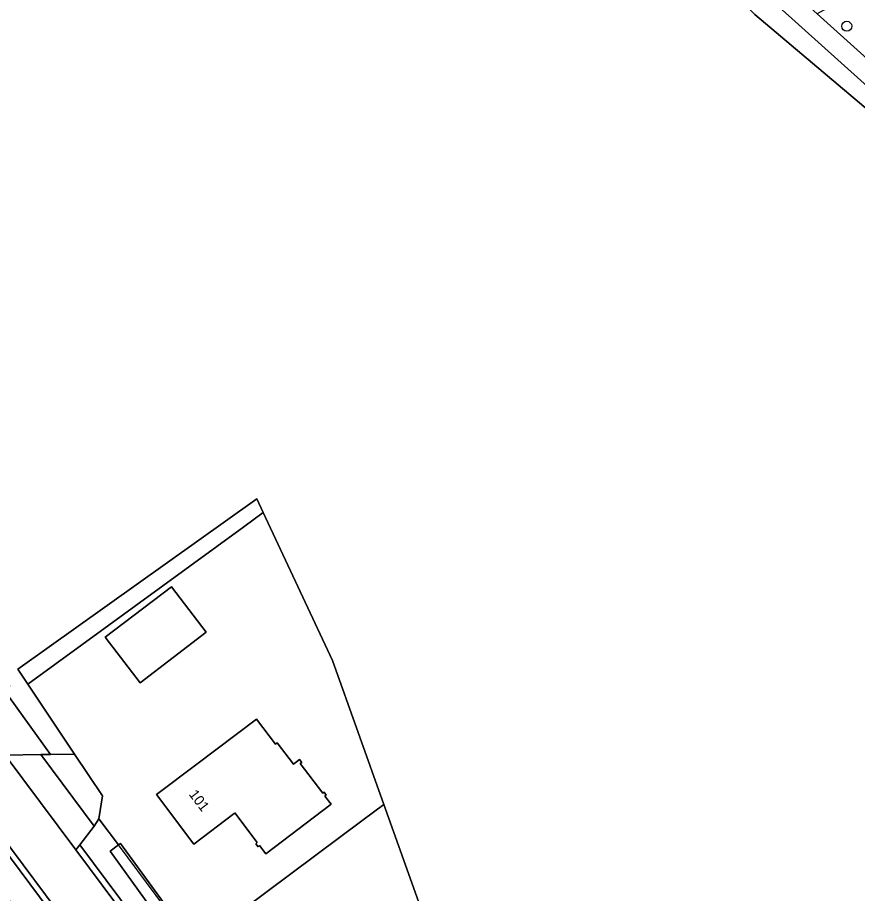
# Model space of a CAD drawing. Extents: x 164494 to 166241, y 382475 to 384495.
# Drawn here: x 164921.5 to 165004.2, y 383333.2 to 383419.5 of the extents above; entities that cross this region are included whole.
import ezdxf

# ---------------------------------------------------------------- set-up
doc = ezdxf.new("R2010")
doc.units = 0
for name, color, linetype in [('IMGEO_Berm_halfverhard', 7, 'Continuous'), ('IMGEO_Boom', 7, 'Continuous'), ('IMGEO_Bouwland', 7, 'Continuous'), ('IMGEO_Erf', 7, 'Continuous'), ('IMGEO_Grasland_overig', 7, 'Continuous'), ('IMGEO_Groenvoorziening', 7, 'Continuous'), ('IMGEO_Hek', 7, 'Continuous'), ('IMGEO_Loofbos', 7, 'Continuous'), ('IMGEO_Pand', 7, 'Continuous'), ('IMGEO_Pand_nummerreeks', 7, 'Continuous'), ('IMGEO_Parkeervlak_open', 7, 'Continuous'), ('IMGEO_Rijbaan_lokaal_gesloten', 7, 'Continuous'), ('IMGEO_Voetpad_open', 7, 'Continuous'), ('IMGEO_Waterloop', 7, 'Continuous')]:
    doc.layers.add(name, color=color, linetype=linetype)

msp = doc.modelspace()

# ---------------------------------------------------------------- linework, layer by layer
at = {"layer": 'IMGEO_Berm_halfverhard'}
msp.add_lwpolyline([(164867.512, 383408.316), (164897.147, 383368.52), (164898.891, 383366.181), (164946.531, 383302.21), (164947.016, 383302.564), (164899.311, 383366.621), (164897.533, 383369.007), (164867.994, 383408.673)], dxfattribs=at)
msp.add_lwpolyline([(164927.659, 383338.025), (164927.281, 383337.528), (164949.568, 383307.631), (164950.049, 383307.989)], close=True, dxfattribs=at)
at = {"layer": 'IMGEO_Boom'}
msp.add_circle((165003.188, 383418.608), 0.489, dxfattribs=at)
at = {"layer": 'IMGEO_Bouwland'}
for points in [[(165060.094, 383385.823), (165046.933, 383390.448), (165039.93, 383393.368), (165039.139, 383393.397), (165024.547, 383396.41), (165016.215, 383401.117), (164994.138, 383419.758), (164976.25, 383437.136), (164945.936, 383468.751), (164939.064, 383467.989)], [(164920.808, 383353.647), (164920.309, 383353.536), (164920.048, 383353.519), (164920.321, 383353.128), (164920.745, 383352.521), (164924.765, 383346.92), (164927.15, 383346.95), (164922.544, 383353.832), (164921.547, 383355.321), (164945.08, 383372.094), (164945.721, 383370.725), (164952.534, 383356.179), (164957.606, 383341.995), (164967.101, 383315.443)]]:
    msp.add_lwpolyline(points, dxfattribs=at)
at = {"layer": 'IMGEO_Erf'}
for points in [[(164952.534, 383356.179), (164945.721, 383370.725), (164943.812, 383369.334), (164922.544, 383353.832), (164927.15, 383346.95), (164929.893, 383342.853), (164929.545, 383340.596), (164931.465, 383338.015), (164931.657, 383338.164), (164938.976, 383328.124), (164955.575, 383340.483), (164957.606, 383341.995)], [(164933.586, 383353.98), (164930.165, 383358.458), (164936.684, 383363.438), (164940.105, 383358.961)], [(164945.044, 383350.408), (164946.916, 383347.935), (164947.109, 383348.081), (164948.704, 383345.973), (164949.297, 383346.422), (164949.515, 383346.135), (164949.371, 383346.027), (164951.584, 383343.103), (164951.716, 383343.202), (164951.93, 383342.919), (164951.798, 383342.82), (164952.408, 383342.014), (164945.967, 383337.14), (164945.352, 383337.954), (164945.208, 383337.845), (164944.991, 383338.132), (164945.134, 383338.241), (164942.922, 383341.164), (164942.872, 383341.126), (164938.884, 383338.108), (164935.209, 383342.965), (164939.196, 383345.983)]]:
    msp.add_lwpolyline(points, close=True, dxfattribs=at)
at = {"layer": 'IMGEO_Grasland_overig'}
for points in [[(165015.733, 383405.906), (165000.271, 383419.83), (164993.985, 383425.491), (164947.396, 383471.597), (164943.78, 383478.232), (164943.191, 383479.313), (164943.19, 383479.35), (164943.115, 383481.884), (164941.103, 383482.279), (164941.181, 383479.625), (164941.206, 383478.776), (164945.886, 383470.277), (164992.612, 383424.036), (165014.572, 383404.259)], [(165099.425, 383315.013), (165092.197, 383334.924), (165086.24, 383357.128), (165076.785, 383375.884), (165072.749, 383381.958), (165062.554, 383397.301), (165051.511, 383396.474), (165026.953, 383397.574), (165014.572, 383404.259), (164992.612, 383424.036), (164945.886, 383470.277), (164941.206, 383478.776), (164939.069, 383479.227)], [(164939.064, 383467.989), (164945.936, 383468.751), (164976.25, 383437.136), (164994.138, 383419.758), (165016.215, 383401.117), (165024.547, 383396.41), (165039.139, 383393.397), (165039.93, 383393.368), (165059.663, 383392.644), (165063.093, 383390.374), (165077.781, 383368.198), (165082.253, 383356.239), (165083.125, 383346.054), (165094.168, 383312.876)]]:
    msp.add_lwpolyline(points, dxfattribs=at)
msp.add_lwpolyline([(164922.544, 383353.832), (164943.812, 383369.334), (164945.721, 383370.725), (164945.08, 383372.094), (164921.547, 383355.321)], close=True, dxfattribs=at)
at = {"layer": 'IMGEO_Groenvoorziening'}
msp.add_lwpolyline([(165062.17, 383406.132), (165060.47, 383406.611), (165056.452, 383408.374), (165056.931, 383414.892), (165055.014, 383422.465), (165049.654, 383435.786), (165044.47, 383438.377), (165038.766, 383439.403), (165031.86, 383438.024), (165023.355, 383436.478), (165016.577, 383428.315), (165003.152, 383421.478), (165000.271, 383419.83), (165015.733, 383405.906), (165027.5, 383399.551), (165051.481, 383398.477), (165062.17, 383399.278)], close=True, dxfattribs=at)
for points in [[(164947.016, 383302.564), (164946.531, 383302.21), (164898.891, 383366.181), (164896.813, 383364.002), (164902.872, 383356.577), (164911.399, 383344.917), (164923.309, 383329.117), (164956.871, 383285.126), (164961.245, 383279.38), (164965.055, 383274.376), (164963.613, 383272.68), (164965.557, 383269.946), (164970.169, 383263.46), (164975.852, 383258.131), (164986.059, 383239.833), (164986.709, 383240.204), (164987.609, 383238.932), (164987.636, 383240.128), (164988.453, 383240.018), (165001.41, 383221.726)], [(164931.465, 383338.015), (164929.545, 383340.596), (164929.058, 383339.863), (164927.659, 383338.025), (164950.049, 383307.989), (164949.568, 383307.631), (164951.985, 383304.388), (164961.639, 383291.401), (164963.99, 383288.228), (164964.472, 383288.585), (164979.896, 383267.671), (164979.765, 383267.573), (164980.598, 383266.49)], [(164965.877, 383288.405), (164963.265, 383291.951), (164961.672, 383294.774), (164957.743, 383299.844), (164954.375, 383304.592), (164952.798, 383306.376), (164950.606, 383309.661), (164948.931, 383311.645), (164947.057, 383314.629), (164930.651, 383337.387), (164931.465, 383338.015)]]:
    msp.add_lwpolyline(points, dxfattribs=at)
at = {"layer": 'IMGEO_Hek'}
for points in [[(164943.812, 383369.334), (164945.721, 383370.725)], [(164922.544, 383353.832), (164943.812, 383369.334)], [(164927.15, 383346.95), (164922.544, 383353.832)], [(164929.545, 383340.596), (164929.893, 383342.853), (164927.15, 383346.95)], [(164931.465, 383338.015), (164929.545, 383340.596)], [(164938.876, 383328.05), (164931.465, 383338.015)]]:
    msp.add_lwpolyline(points, dxfattribs=at)
at = {"layer": 'IMGEO_Loofbos'}
msp.add_lwpolyline([(164967.101, 383315.443), (164957.606, 383341.995), (164955.575, 383340.483), (164938.976, 383328.124), (164943.74, 383321.588), (164947.361, 383316.088), (164952.187, 383309.591), (164955.054, 383305.726)], close=True, dxfattribs=at)
at = {"layer": 'IMGEO_Pand'}
for points in [[(164933.586, 383353.98), (164940.105, 383358.961), (164936.684, 383363.438), (164930.165, 383358.458)], [(164949.371, 383346.027), (164949.515, 383346.135), (164949.297, 383346.422), (164948.704, 383345.973), (164947.109, 383348.081), (164946.916, 383347.935), (164945.044, 383350.408), (164939.196, 383345.983), (164935.209, 383342.965), (164938.884, 383338.108), (164942.872, 383341.126), (164942.922, 383341.164), (164945.134, 383338.241), (164944.991, 383338.132), (164945.208, 383337.845), (164945.352, 383337.954), (164945.967, 383337.14), (164952.408, 383342.014), (164951.798, 383342.82), (164951.93, 383342.919), (164951.716, 383343.202), (164951.584, 383343.103)]]:
    msp.add_lwpolyline(points, close=True, dxfattribs=at)
at = {"layer": 'IMGEO_Parkeervlak_open'}
msp.add_lwpolyline([(164920.745, 383352.521), (164920.321, 383353.128), (164917.658, 383351.268), (164917.265, 383350.994), (164920.32, 383346.864), (164923.81, 383346.908), (164924.765, 383346.92)], close=True, dxfattribs=at)
at = {"layer": 'IMGEO_Rijbaan_lokaal_gesloten'}
for points in [[(164951.985, 383304.388), (164949.568, 383307.631), (164927.281, 383337.528), (164920.32, 383346.864), (164917.265, 383350.994), (164917.166, 383350.925), (164910.131, 383360.313), (164904.989, 383367.182), (164899.015, 383375.227), (164889.835, 383387.688), (164882.427, 383397.698), (164873.759, 383409.297), (164866.112, 383419.793), (164858.241, 383430.867), (164853.395, 383438.04), (164848.569, 383445.498), (164846.561, 383448.854), (164846.701, 383448.936), (164846.632, 383449.047)], [(164867.994, 383408.673), (164897.533, 383369.007), (164899.311, 383366.621), (164947.016, 383302.564), (164947.902, 383301.374), (164951.985, 383304.388)]]:
    msp.add_lwpolyline(points, dxfattribs=at)
at = {"layer": 'IMGEO_Voetpad_open'}
for points in [[(164929.058, 383339.863), (164923.81, 383346.908), (164920.32, 383346.864), (164927.281, 383337.528), (164927.659, 383338.025)], [(164927.15, 383346.95), (164924.765, 383346.92), (164923.81, 383346.908), (164929.058, 383339.863), (164929.545, 383340.596), (164929.893, 383342.853)]]:
    msp.add_lwpolyline(points, close=True, dxfattribs=at)
at = {"layer": 'IMGEO_Waterloop'}
msp.add_lwpolyline([(164967.017, 383288.822), (164967.059, 383289.542), (164955.054, 383305.726), (164952.187, 383309.591), (164947.361, 383316.088), (164943.74, 383321.588), (164938.976, 383328.124), (164931.657, 383338.164), (164931.465, 383338.015), (164930.651, 383337.387), (164947.057, 383314.629), (164948.931, 383311.645), (164950.606, 383309.661), (164952.798, 383306.376), (164954.375, 383304.592), (164957.743, 383299.844), (164961.672, 383294.774), (164963.265, 383291.951), (164965.877, 383288.405)], dxfattribs=at)

# ---------------------------------------------------------------- texts
at = {"layer": 'IMGEO_Pand_nummerreeks'}
msp.add_text('101', height=1, rotation=307.11027, dxfattribs=at).set_placement((164938.348, 383342.993))

doc.saveas('drawing.dxf')
